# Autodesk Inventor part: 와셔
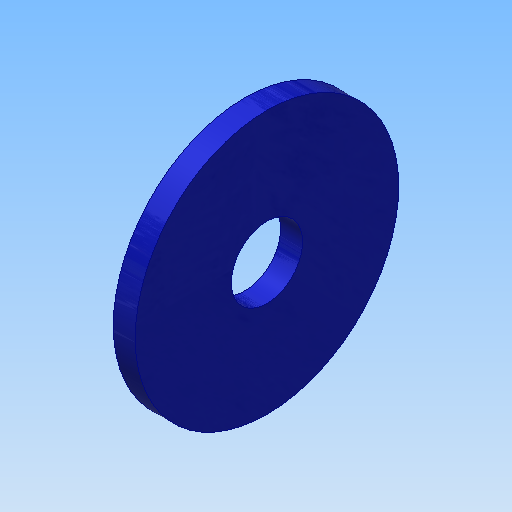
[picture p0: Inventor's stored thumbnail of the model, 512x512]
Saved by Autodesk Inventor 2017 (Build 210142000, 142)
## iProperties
Created: 2015-12
Part Number: 와셔
Material: 스테인리스강
Document SubType Name: Modeling
Designer: mduedu
Density: 8.08 g/cm^3
Mass: 6.77437 g
Surface Area: 10.3005 cm^2
Volume: 0.838413 cm^3
Appearance: 파란색 - 벽 페인트 - 광택
Author: mduedu
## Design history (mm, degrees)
sketch "스케치1"
  geometry: C1 r 3.25 at (0, 0); C2 r 12 at (0, 0); 1 further point
  constraints: 2 centre point, 2 coincident
  dimensions: "d0" = 6.5 diameter of C1; "d1" = 24 diameter of C2
extrude "돌출1" new body sketch "스케치1" stored distance "d2" = 2; taper "d3" = 0 deg
node "솔리드1"
